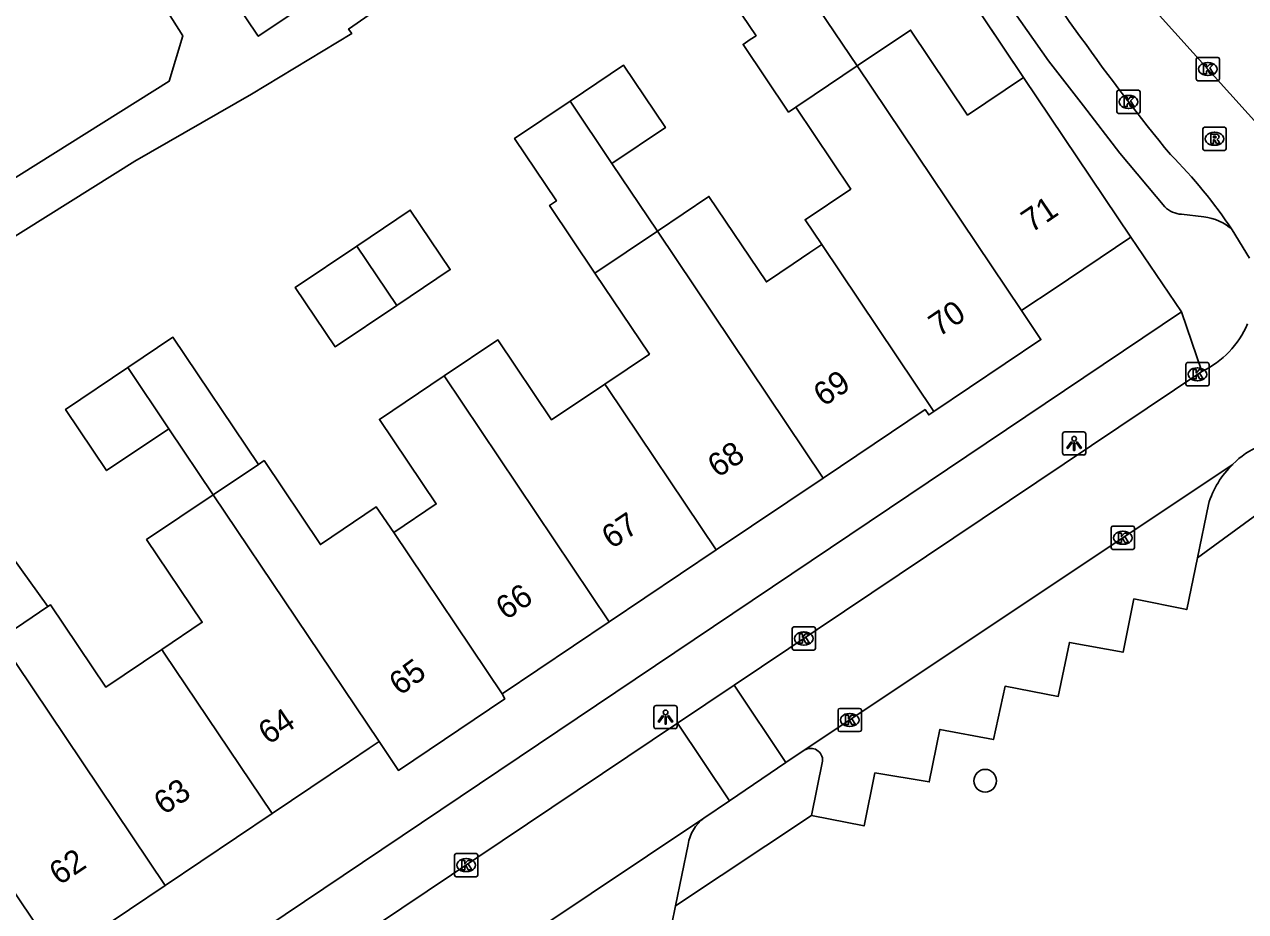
# Model space of a CAD drawing. Extents: x 158352 to 159489, y 383828 to 384597.
# Drawn here: x 158936.2 to 158988.7, y 384167.6 to 384205.7 of the extents above; entities that cross this region are included whole.
import ezdxf

# ---------------------------------------------------------------- set-up
doc = ezdxf.new("R2010")
doc.units = 0
for name, color, linetype in [('IMGEO_Boom', 7, 'Continuous'), ('IMGEO_Kolk', 7, 'Continuous'), ('IMGEO_Lichtpunt', 7, 'Continuous'), ('IMGEO_Muur', 7, 'Continuous'), ('IMGEO_Pand', 7, 'Continuous'), ('IMGEO_Pand_nummerreeks', 7, 'Continuous'), ('IMGEO_Parkeervlak_open', 7, 'Continuous'), ('IMGEO_Rijbaan_lokaal_open', 7, 'Continuous'), ('IMGEO_Rioolput', 7, 'Continuous'), ('IMGEO_Voetpad_open', 7, 'Continuous')]:
    doc.layers.add(name, color=color, linetype=linetype)

msp = doc.modelspace()

# ---------------------------------------------------------------- linework, layer by layer
at = {"layer": 'IMGEO_Boom'}
msp.add_circle((158977.532, 384173.212), 0.489, dxfattribs=at)
at = {"layer": 'IMGEO_Kolk'}
for p, q in [((158986.605, 384203.383), (158986.605, 384204.235)), ((158986.68, 384204.309), (158987.532, 384204.309)), ((158987.093, 384204.089), (158987.118, 384204.089)), ((158987.606, 384204.235), (158987.606, 384203.383)), ((158987.116, 384203.529), (158987.091, 384203.529)), ((158987.532, 384203.309), (158986.68, 384203.309)), ((158983.196, 384201.972), (158983.196, 384202.824)), ((158983.271, 384202.898), (158984.123, 384202.898)), ((158983.684, 384202.678), (158983.709, 384202.678)), ((158984.197, 384202.824), (158984.197, 384201.972)), ((158984.123, 384201.898), (158983.271, 384201.898)), ((158983.707, 384202.118), (158983.682, 384202.118)), ((158986.163, 384190.261), (158986.163, 384191.113)), ((158986.238, 384191.187), (158987.09, 384191.187)), ((158986.651, 384190.967), (158986.676, 384190.967)), ((158987.164, 384191.113), (158987.164, 384190.261)), ((158986.674, 384190.407), (158986.649, 384190.407)), ((158987.09, 384190.187), (158986.238, 384190.187)), ((158982.951, 384183.234), (158982.951, 384184.086)), ((158983.026, 384184.16), (158983.878, 384184.16)), ((158983.952, 384184.086), (158983.952, 384183.234)), ((158983.439, 384183.94), (158983.464, 384183.94)), ((158983.878, 384183.16), (158983.026, 384183.16)), ((158983.462, 384183.38), (158983.437, 384183.38)), ((158969.306, 384179.829), (158970.158, 384179.829)), ((158969.231, 384178.903), (158969.231, 384179.755)), ((158969.719, 384179.609), (158969.744, 384179.609)), ((158970.232, 384179.755), (158970.232, 384178.903)), ((158970.158, 384178.829), (158969.306, 384178.829)), ((158969.742, 384179.049), (158969.717, 384179.049)), ((158971.207, 384175.401), (158971.207, 384176.253)), ((158971.282, 384176.327), (158972.134, 384176.327)), ((158972.208, 384176.253), (158972.208, 384175.401)), ((158971.695, 384176.107), (158971.72, 384176.107)), ((158972.134, 384175.327), (158971.282, 384175.327)), ((158971.718, 384175.547), (158971.693, 384175.547)), ((158954.711, 384169.161), (158954.711, 384170.013)), ((158954.786, 384170.087), (158955.638, 384170.087)), ((158955.199, 384169.867), (158955.224, 384169.867)), ((158955.712, 384170.013), (158955.712, 384169.161)), ((158955.222, 384169.307), (158955.197, 384169.307)), ((158955.638, 384169.087), (158954.786, 384169.087))]:
    msp.add_line(p, q, dxfattribs=at)
for points in [[(158986.605, 384203.383), (158986.605, 384204.235)], [(158986.68, 384204.309), (158987.532, 384204.309)], [(158986.926, 384204.009), (158987.049, 384204.009), (158987.049, 384203.858), (158987.179, 384204.009), (158987.343, 384204.009), (158987.197, 384203.858), (158987.35, 384203.609), (158987.198, 384203.609), (158987.113, 384203.773), (158987.049, 384203.706), (158987.049, 384203.609), (158986.926, 384203.609), (158986.926, 384204.009)], [(158987.606, 384204.235), (158987.606, 384203.383)], [(158987.532, 384203.309), (158986.68, 384203.309)], [(158983.196, 384201.972), (158983.196, 384202.824)], [(158983.271, 384202.898), (158984.123, 384202.898)], [(158983.517, 384202.598), (158983.64, 384202.598), (158983.64, 384202.447), (158983.77, 384202.598), (158983.934, 384202.598), (158983.788, 384202.447), (158983.941, 384202.198), (158983.789, 384202.198), (158983.704, 384202.362), (158983.64, 384202.295), (158983.64, 384202.198), (158983.517, 384202.198), (158983.517, 384202.598)], [(158984.197, 384202.824), (158984.197, 384201.972)], [(158984.123, 384201.898), (158983.271, 384201.898)], [(158986.163, 384190.261), (158986.163, 384191.113)], [(158986.238, 384191.187), (158987.09, 384191.187)], [(158986.484, 384190.887), (158986.607, 384190.887), (158986.607, 384190.736), (158986.737, 384190.887), (158986.901, 384190.887), (158986.755, 384190.736), (158986.908, 384190.487), (158986.756, 384190.487), (158986.671, 384190.651), (158986.607, 384190.584), (158986.607, 384190.487), (158986.484, 384190.487), (158986.484, 384190.887)], [(158987.164, 384191.113), (158987.164, 384190.261)], [(158987.09, 384190.187), (158986.238, 384190.187)], [(158982.951, 384183.234), (158982.951, 384184.086)], [(158983.026, 384184.16), (158983.878, 384184.16)], [(158983.952, 384184.086), (158983.952, 384183.234)], [(158983.272, 384183.86), (158983.395, 384183.86), (158983.395, 384183.709), (158983.525, 384183.86), (158983.689, 384183.86), (158983.543, 384183.709), (158983.696, 384183.46), (158983.544, 384183.46), (158983.459, 384183.624), (158983.395, 384183.557), (158983.395, 384183.46), (158983.272, 384183.46), (158983.272, 384183.86)], [(158983.878, 384183.16), (158983.026, 384183.16)], [(158969.306, 384179.829), (158970.158, 384179.829)], [(158969.231, 384178.903), (158969.231, 384179.755)], [(158969.552, 384179.529), (158969.675, 384179.529), (158969.675, 384179.378), (158969.805, 384179.529), (158969.969, 384179.529), (158969.823, 384179.378), (158969.976, 384179.129), (158969.824, 384179.129), (158969.739, 384179.293), (158969.675, 384179.226), (158969.675, 384179.129), (158969.552, 384179.129), (158969.552, 384179.529)], [(158970.232, 384179.755), (158970.232, 384178.903)], [(158970.158, 384178.829), (158969.306, 384178.829)], [(158971.207, 384175.401), (158971.207, 384176.253)], [(158971.282, 384176.327), (158972.134, 384176.327)], [(158972.208, 384176.253), (158972.208, 384175.401)], [(158971.528, 384176.027), (158971.651, 384176.027), (158971.651, 384175.876), (158971.781, 384176.027), (158971.945, 384176.027), (158971.799, 384175.876), (158971.952, 384175.627), (158971.8, 384175.627), (158971.715, 384175.791), (158971.651, 384175.724), (158971.651, 384175.627), (158971.528, 384175.627), (158971.528, 384176.027)], [(158972.134, 384175.327), (158971.282, 384175.327)], [(158954.711, 384169.161), (158954.711, 384170.013)], [(158954.786, 384170.087), (158955.638, 384170.087)], [(158955.712, 384170.013), (158955.712, 384169.161)], [(158955.032, 384169.787), (158955.155, 384169.787), (158955.155, 384169.636), (158955.285, 384169.787), (158955.449, 384169.787), (158955.303, 384169.636), (158955.456, 384169.387), (158955.304, 384169.387), (158955.219, 384169.551), (158955.155, 384169.484), (158955.155, 384169.387), (158955.032, 384169.387), (158955.032, 384169.787)], [(158955.638, 384169.087), (158954.786, 384169.087)]]:
    msp.add_lwpolyline(points, dxfattribs=at)
for centre, start, end in [((158986.682, 384204.233), 91.552, 178.448), ((158986.682, 384204.233), 91.552, 178.448), ((158987.53, 384204.233), 1.552, 88.448), ((158987.53, 384204.233), 1.552, 88.448), ((158986.682, 384203.385), 181.552, 268.448), ((158986.682, 384203.385), 181.552, 268.448), ((158987.53, 384203.385), 271.552, 358.448), ((158987.53, 384203.385), 271.552, 358.448), ((158983.273, 384202.822), 91.552, 178.448), ((158983.273, 384202.822), 91.552, 178.448), ((158984.121, 384202.822), 1.552, 88.448), ((158984.121, 384202.822), 1.552, 88.448), ((158983.273, 384201.974), 181.552, 268.448), ((158983.273, 384201.974), 181.552, 268.448), ((158984.121, 384201.974), 271.552, 358.448), ((158984.121, 384201.974), 271.552, 358.448), ((158986.24, 384191.111), 91.552, 178.448), ((158986.24, 384191.111), 91.552, 178.448), ((158987.088, 384191.111), 1.552, 88.448), ((158987.088, 384191.111), 1.552, 88.448), ((158986.24, 384190.263), 181.552, 268.448), ((158986.24, 384190.263), 181.552, 268.448), ((158987.088, 384190.263), 271.552, 358.448), ((158987.088, 384190.263), 271.552, 358.448), ((158983.028, 384184.084), 91.552, 178.448), ((158983.028, 384184.084), 91.552, 178.448), ((158983.876, 384184.084), 1.552, 88.448), ((158983.876, 384184.084), 1.552, 88.448), ((158983.028, 384183.236), 181.552, 268.448), ((158983.028, 384183.236), 181.552, 268.448), ((158983.876, 384183.236), 271.552, 358.448), ((158983.876, 384183.236), 271.552, 358.448), ((158969.308, 384179.753), 91.552, 178.448), ((158969.308, 384179.753), 91.552, 178.448), ((158970.156, 384179.753), 1.552, 88.448), ((158970.156, 384179.753), 1.552, 88.448), ((158969.308, 384178.905), 181.552, 268.448), ((158969.308, 384178.905), 181.552, 268.448), ((158970.156, 384178.905), 271.552, 358.448), ((158970.156, 384178.905), 271.552, 358.448), ((158971.284, 384176.251), 91.552, 178.448), ((158971.284, 384176.251), 91.552, 178.448), ((158972.132, 384176.251), 1.552, 88.448), ((158972.132, 384176.251), 1.552, 88.448), ((158971.284, 384175.403), 181.552, 268.448), ((158971.284, 384175.403), 181.552, 268.448), ((158972.132, 384175.403), 271.552, 358.448), ((158972.132, 384175.403), 271.552, 358.448), ((158954.788, 384170.011), 91.552, 178.448), ((158954.788, 384170.011), 91.552, 178.448), ((158955.636, 384170.011), 1.552, 88.448), ((158955.636, 384170.011), 1.552, 88.448), ((158954.788, 384169.163), 181.552, 268.448), ((158954.788, 384169.163), 181.552, 268.448), ((158955.636, 384169.163), 271.552, 358.448), ((158955.636, 384169.163), 271.552, 358.448)]:
    msp.add_arc(centre, 0.0765, start, end, dxfattribs=at)
for centre, major_axis, ratio, start_param, end_param in [((158987.092, 384203.809), (-0.387, 0.002), 0.722429, 4.712389, 7.853982), ((158987.117, 384203.809), (-0.39, 0.002), 0.717154, 1.570796, 4.712389), ((158983.683, 384202.398), (-0.387, 0.002), 0.722429, 4.712389, 7.853982), ((158983.708, 384202.398), (-0.39, 0.002), 0.717154, 1.570796, 4.712389), ((158986.65, 384190.687), (-0.387, 0.002), 0.722429, 4.712389, 7.853982), ((158986.675, 384190.687), (-0.39, 0.002), 0.717154, 1.570796, 4.712389), ((158983.438, 384183.66), (-0.387, 0.002), 0.722429, 4.712389, 7.853982), ((158983.463, 384183.66), (-0.39, 0.002), 0.717154, 1.570796, 4.712389), ((158969.718, 384179.329), (-0.387, 0.002), 0.722429, 4.712389, 7.853982), ((158969.743, 384179.329), (-0.39, 0.002), 0.717154, 1.570796, 4.712389), ((158971.694, 384175.827), (-0.387, 0.002), 0.722429, 4.712389, 7.853982), ((158971.719, 384175.827), (-0.39, 0.002), 0.717154, 1.570796, 4.712389), ((158955.198, 384169.587), (-0.387, 0.002), 0.722429, 4.712389, 7.853982), ((158955.223, 384169.587), (-0.39, 0.002), 0.717154, 1.570796, 4.712389)]:
    msp.add_ellipse(centre, major_axis=major_axis, ratio=ratio, start_param=start_param, end_param=end_param, dxfattribs=at)
at = {"layer": 'IMGEO_Lichtpunt'}
for p, q in [((158981.763, 384188.214), (158980.955, 384188.214)), ((158981.763, 384188.214), (158980.955, 384188.214)), ((158980.861, 384188.119), (158980.861, 384187.312)), ((158980.861, 384188.119), (158980.861, 384187.312)), ((158981.857, 384187.312), (158981.857, 384188.119)), ((158981.857, 384187.312), (158981.857, 384188.119)), ((158980.955, 384187.218), (158981.763, 384187.218)), ((158980.955, 384187.218), (158981.763, 384187.218)), ((158963.288, 384176.355), (158963.288, 384175.548)), ((158963.288, 384176.355), (158963.288, 384175.548)), ((158964.19, 384176.45), (158963.382, 384176.45)), ((158964.19, 384176.45), (158963.382, 384176.45)), ((158964.284, 384175.548), (158964.284, 384176.355)), ((158964.284, 384175.548), (158964.284, 384176.355)), ((158963.382, 384175.454), (158964.19, 384175.454)), ((158963.382, 384175.454), (158964.19, 384175.454))]:
    msp.add_line(p, q, dxfattribs=at)
for points in [[(158981.235, 384187.783), (158981.274, 384187.755), (158981.086, 384187.493), (158981.048, 384187.52), (158981.235, 384187.783)], [(158981.337, 384187.735), (158981.384, 384187.735), (158981.384, 384187.413), (158981.337, 384187.413), (158981.337, 384187.735)], [(158981.447, 384187.755), (158981.485, 384187.782), (158981.672, 384187.52), (158981.633, 384187.492), (158981.447, 384187.755)], [(158963.662, 384176.019), (158963.701, 384175.991), (158963.513, 384175.729), (158963.475, 384175.756), (158963.662, 384176.019)], [(158963.764, 384175.971), (158963.811, 384175.971), (158963.811, 384175.649), (158963.764, 384175.649), (158963.764, 384175.971)], [(158963.874, 384175.991), (158963.912, 384176.018), (158964.099, 384175.756), (158964.06, 384175.728), (158963.874, 384175.991)]]:
    msp.add_lwpolyline(points, dxfattribs=at)
for centre in [(158981.36, 384187.917), (158963.787, 384176.153)]:
    msp.add_circle(centre, 0.0994, dxfattribs=at)
for centre, start, end in [((158980.955, 384188.119), 90, 180), ((158980.955, 384188.119), 90, 180), ((158981.763, 384188.119), 0, 90), ((158981.763, 384188.119), 0, 90), ((158980.955, 384187.312), 180, 270), ((158980.955, 384187.312), 180, 270), ((158981.763, 384187.312), 270, 0), ((158981.763, 384187.312), 270, 360), ((158963.382, 384176.355), 90, 180), ((158963.382, 384176.355), 90, 180), ((158964.19, 384176.355), 0, 90), ((158964.19, 384176.355), 0, 90), ((158963.382, 384175.548), 180, 270), ((158963.382, 384175.548), 180, 270), ((158964.19, 384175.548), 270, 0), ((158964.19, 384175.548), 270, 360)]:
    msp.add_arc(centre, 0.0946, start, end, dxfattribs=at)
at = {"layer": 'IMGEO_Muur'}
msp.add_lwpolyline([(158968.988, 384218.666), (158979.183, 384203.447)], dxfattribs=at)
at = {"layer": 'IMGEO_Pand'}
for points in [[(158968.271, 384209.526), (158965.882, 384207.922), (158967.683, 384205.24), (158967.433, 384205.072), (158967.124, 384204.865), (158969.077, 384201.96), (158969.386, 384202.167)], [(158972.026, 384203.94), (158970.073, 384206.845)], [(158979.183, 384203.447), (158976.776, 384201.83), (158974.323, 384205.483), (158972.026, 384203.94)], [(158959.681, 384202.428), (158961.982, 384203.973), (158963.783, 384201.291), (158961.483, 384199.747)], [(158972.026, 384203.94), (158970.173, 384202.696), (158969.386, 384202.167)], [(158972.026, 384203.94), (158979.096, 384193.423)], [(158979.183, 384203.447), (158983.795, 384196.582)], [(158959.681, 384202.428), (158957.292, 384200.824), (158959.093, 384198.142), (158958.797, 384197.943), (158960.75, 384195.037)], [(158961.483, 384199.747), (158959.681, 384202.428)], [(158969.386, 384202.167), (158971.749, 384198.651), (158969.787, 384197.332), (158970.506, 384196.262)], [(158963.436, 384196.842), (158961.483, 384199.747)], [(158970.506, 384196.262), (158969.998, 384195.921), (158969.278, 384195.438), (158968.122, 384194.661), (158965.655, 384198.333), (158963.436, 384196.842)], [(158952.226, 384193.646), (158954.525, 384195.189), (158952.809, 384197.745), (158950.508, 384196.2)], [(158960.75, 384195.037), (158963.436, 384196.842)], [(158963.436, 384196.842), (158970.571, 384186.228)], [(158950.508, 384196.2), (158947.861, 384194.423), (158949.577, 384191.868), (158952.226, 384193.646)], [(158950.508, 384196.2), (158952.226, 384193.646)], [(158975.327, 384189.089), (158970.506, 384196.262)], [(158979.096, 384193.423), (158979.244, 384193.523), (158980.454, 384194.336), (158983.795, 384196.582)], [(158961.176, 384190.267), (158963.091, 384191.553), (158960.75, 384195.037)], [(158975.327, 384189.089), (158979.93, 384192.182), (158979.096, 384193.423)], [(158946.278, 384186.814), (158942.604, 384192.281), (158940.659, 384190.975)], [(158954.263, 384190.614), (158956.576, 384192.168), (158958.887, 384188.729), (158961.176, 384190.267)], [(158940.659, 384190.975), (158937.984, 384189.179), (158939.751, 384186.547), (158942.429, 384188.345)], [(158942.429, 384188.345), (158940.659, 384190.975)], [(158952.102, 384183.889), (158953.924, 384185.113), (158951.483, 384188.746), (158954.263, 384190.614)], [(158961.367, 384180.044), (158954.263, 384190.614)], [(158961.176, 384190.267), (158961.302, 384190.08), (158965.969, 384183.136)], [(158970.571, 384186.228), (158974.95, 384189.17), (158975.105, 384188.94), (158975.327, 384189.089)], [(158942.429, 384188.345), (158944.335, 384185.508)], [(158946.278, 384186.814), (158944.335, 384185.508)], [(158952.102, 384183.889), (158951.343, 384184.983), (158948.943, 384183.37), (158946.52, 384186.976), (158946.278, 384186.814)], [(158970.571, 384186.228), (158965.969, 384183.136)], [(158937.224, 384180.707), (158933.41, 384185.998), (158931.546, 384184.655)], [(158942.122, 384178.862), (158943.86, 384180.03), (158941.472, 384183.584), (158944.335, 384185.508)], [(158944.335, 384185.508), (158951.466, 384174.899)], [(158956.765, 384176.951), (158952.102, 384183.889)], [(158965.969, 384183.136), (158961.367, 384180.044)], [(158937.224, 384180.707), (158935.141, 384179.308)], [(158942.122, 384178.862), (158939.71, 384177.241), (158937.332, 384180.78), (158937.224, 384180.707)], [(158961.367, 384180.044), (158956.765, 384176.951)], [(158935.141, 384179.308), (158942.263, 384168.715)], [(158946.864, 384171.806), (158942.229, 384178.703), (158942.122, 384178.862)], [(158951.466, 384174.899), (158952.299, 384173.659), (158956.873, 384176.732), (158956.765, 384176.951)], [(158951.466, 384174.899), (158951.048, 384174.618), (158950.2, 384174.048), (158946.864, 384171.806)], [(158932.968, 384172.604), (158937.66, 384165.622)], [(158942.263, 384168.715), (158946.864, 384171.806)], [(158942.263, 384168.715), (158937.66, 384165.622)]]:
    msp.add_lwpolyline(points, dxfattribs=at)
at = {"layer": 'IMGEO_Parkeervlak_open'}
for points in [[(158970.067, 384171.724), (158972.327, 384171.272), (158972.793, 384173.549), (158975.131, 384173.161), (158975.587, 384175.42), (158977.887, 384174.985), (158978.392, 384177.276), (158980.673, 384176.841), (158981.155, 384179.159), (158983.46, 384178.737), (158983.928, 384181.032), (158986.198, 384180.57), (158986.658, 384182.799)], [(158943.936, 384154.326), (158946.333, 384153.827), (158946.816, 384156.22), (158949.22, 384155.771), (158949.725, 384158.18), (158952.106, 384157.731), (158952.582, 384160.203), (158955.01, 384159.702), (158955.523, 384162.086), (158957.941, 384161.655), (158958.467, 384164.069), (158960.887, 384163.61), (158961.363, 384165.968), (158963.745, 384165.513), (158964.22, 384167.84)]]:
    msp.add_lwpolyline(points, dxfattribs=at)
at = {"layer": 'IMGEO_Rijbaan_lokaal_open'}
for points in [[(158969.101, 384223.918), (158981.145, 384205.847), (158981.637, 384205.183)], [(158983.668, 384207.891), (158984.272, 384207.041), (158984.897, 384206.251), (158990.424, 384200.141)], [(158988.153, 384196.891), (158988.895, 384195.685)], [(158986.851, 384190.812), (158966.736, 384177.317)], [(158988.183, 384186.816), (158969.755, 384174.527)], [(158964.303, 384175.685), (158966.736, 384177.317)], [(158966.736, 384177.317), (158968.966, 384173.995)], [(158940.594, 384159.779), (158964.303, 384175.685)], [(158964.303, 384175.685), (158966.537, 384172.358)], [(158968.966, 384173.995), (158969.755, 384174.527)], [(158968.966, 384173.995), (158966.537, 384172.358)], [(158966.537, 384172.358), (158965.432, 384171.613)], [(158965.432, 384171.613), (158943.586, 384157)]]:
    msp.add_lwpolyline(points, dxfattribs=at)
for centre, radius, start, end in [((159055.168, 384257.45), 90.214, 215.40621, 219.4441), ((158970.761, 384185.374), 20.86, 33.5119, 45.0419), ((158985.182, 384194.375), 3.935, 295.1026, 337.273), ((158990.49, 384184.657), 3.16, 85.805, 136.8919)]:
    msp.add_arc(centre, radius, start, end, dxfattribs=at)
at = {"layer": 'IMGEO_Rioolput'}
for p, q in [((158986.893, 384200.384), (158986.893, 384201.236)), ((158986.968, 384201.31), (158987.82, 384201.31)), ((158987.381, 384201.09), (158987.406, 384201.09)), ((158987.894, 384201.236), (158987.894, 384200.384)), ((158987.82, 384200.31), (158986.968, 384200.31)), ((158987.404, 384200.53), (158987.379, 384200.53))]:
    msp.add_line(p, q, dxfattribs=at)
for points in [[(158986.893, 384200.384), (158986.893, 384201.236)], [(158986.968, 384201.31), (158987.82, 384201.31)], [(158987.482, 384201.008), (158987.23, 384201.01), (158987.23, 384200.61)], [(158987.408, 384200.929), (158987.354, 384200.929), (158987.354, 384200.848)], [(158987.354, 384200.848), (158987.406, 384200.848)], [(158987.894, 384201.236), (158987.894, 384200.384)], [(158987.82, 384200.31), (158986.968, 384200.31)], [(158987.23, 384200.61), (158987.354, 384200.61), (158987.354, 384200.772), (158987.365, 384200.772)], [(158987.412, 384200.743), (158987.483, 384200.61), (158987.623, 384200.61), (158987.558, 384200.736)]]:
    msp.add_lwpolyline(points, dxfattribs=at)
for centre, radius, start, end in [((158986.97, 384201.234), 0.0765, 91.552, 178.448), ((158986.97, 384201.234), 0.0765, 91.552, 178.448), ((158987.39, 384201.037), 0.19, 274.7715, 282.9687), ((158987.414, 384200.833), 0.0964, 77.0061, 93.1865), ((158987.428, 384200.89), 0.0378, 276.6634, 79.6772), ((158987.481, 384200.898), 0.109, 350.3612, 89.416), ((158987.479, 384200.898), 0.112, 277.5842, 350.9817), ((158987.818, 384201.234), 0.0765, 1.552, 88.448), ((158987.818, 384201.234), 0.0765, 1.552, 88.448), ((158986.97, 384200.386), 0.0765, 181.552, 268.448), ((158986.97, 384200.386), 0.0765, 181.552, 268.448), ((158987.364, 384200.719), 0.0533, 26.0293, 88.6989), ((158987.463, 384200.683), 0.108, 29.5134, 73.7905), ((158987.818, 384200.386), 0.0765, 271.552, 358.448), ((158987.818, 384200.386), 0.0765, 271.552, 358.448)]:
    msp.add_arc(centre, radius, start, end, dxfattribs=at)
for centre, major_axis, ratio, start_param, end_param in [((158987.38, 384200.81), (-0.387, 0.002), 0.722429, 4.712389, 7.853982), ((158987.405, 384200.81), (-0.39, 0.002), 0.717154, 1.570796, 4.712389)]:
    msp.add_ellipse(centre, major_axis=major_axis, ratio=ratio, start_param=start_param, end_param=end_param, dxfattribs=at)
at = {"layer": 'IMGEO_Voetpad_open'}
for points in [[(158985.257, 384197.887), (158983.319, 384200.198), (158981.756, 384202.225), (158980.257, 384204.158), (158978.154, 384207.172), (158972.077, 384216.274)], [(158961.437, 384215.4), (158948.662, 384206.821), (158946.272, 384205.215), (158943.226, 384209.75), (158940.311, 384214.091), (158938.32, 384212.669), (158943.028, 384205.234), (158942.435, 384203.284), (158930.336, 384195.705), (158931.464, 384193.904), (158940.958, 384199.85), (158945.987, 384202.726), (158950.289, 384205.339), (158950.159, 384205.525), (158964.25, 384215.304)], [(158971.862, 384214.376), (158979.183, 384203.447)], [(158986.942, 384197.449), (158985.98, 384197.566)], [(158983.795, 384196.582), (158985.981, 384193.365)], [(158985.981, 384193.365), (158902.964, 384137.583)], [(158985.981, 384193.365), (158986.851, 384190.812)], [(158986.658, 384182.799), (158987.133, 384185.095)], [(158986.658, 384182.799), (158989.43, 384184.811), (158993.685, 384184.282)], [(158970.54, 384174.054), (158970.067, 384171.724)], [(158964.22, 384167.84), (158970.067, 384171.724)], [(158964.759, 384170.476), (158964.22, 384167.84)]]:
    msp.add_lwpolyline(points, dxfattribs=at)
for centre, radius, start, end in [((158986.048, 384198.695), 1.131, 225.5857, 266.5334), ((158986.758, 384195.457), 2.001, 45.7983, 84.7234), ((158990.905, 384183.974), 3.935, 133.7709, 163.4535), ((158970.03, 384174.096), 0.512, 355.3201, 122.5379), ((158966.502, 384170.212), 1.763, 127.3713, 171.3853)]:
    msp.add_arc(centre, radius, start, end, dxfattribs=at)

# ---------------------------------------------------------------- texts
at = {"layer": 'IMGEO_Pand_nummerreeks'}
for s, rotation, p in [('71', 33.9076, (158979.521, 384196.746)), ('70', 33.8905, (158975.54, 384192.269)), ('69', 33.8962, (158970.582, 384189.271)), ('68', 33.8979, (158966.032, 384186.214)), ('67', 33.8979, (158961.476, 384183.153)), ('66', 33.8979, (158956.923, 384180.094)), ('65', 36.3885, (158952.371, 384176.845)), ('64', 33.9019, (158946.709, 384174.739)), ('63', 33.9019, (158942.214, 384171.719)), ('62', 33.8992, (158937.718, 384168.696))]:
    msp.add_text(s, height=1, rotation=rotation, dxfattribs=at).set_placement(p)

doc.saveas('drawing.dxf')
